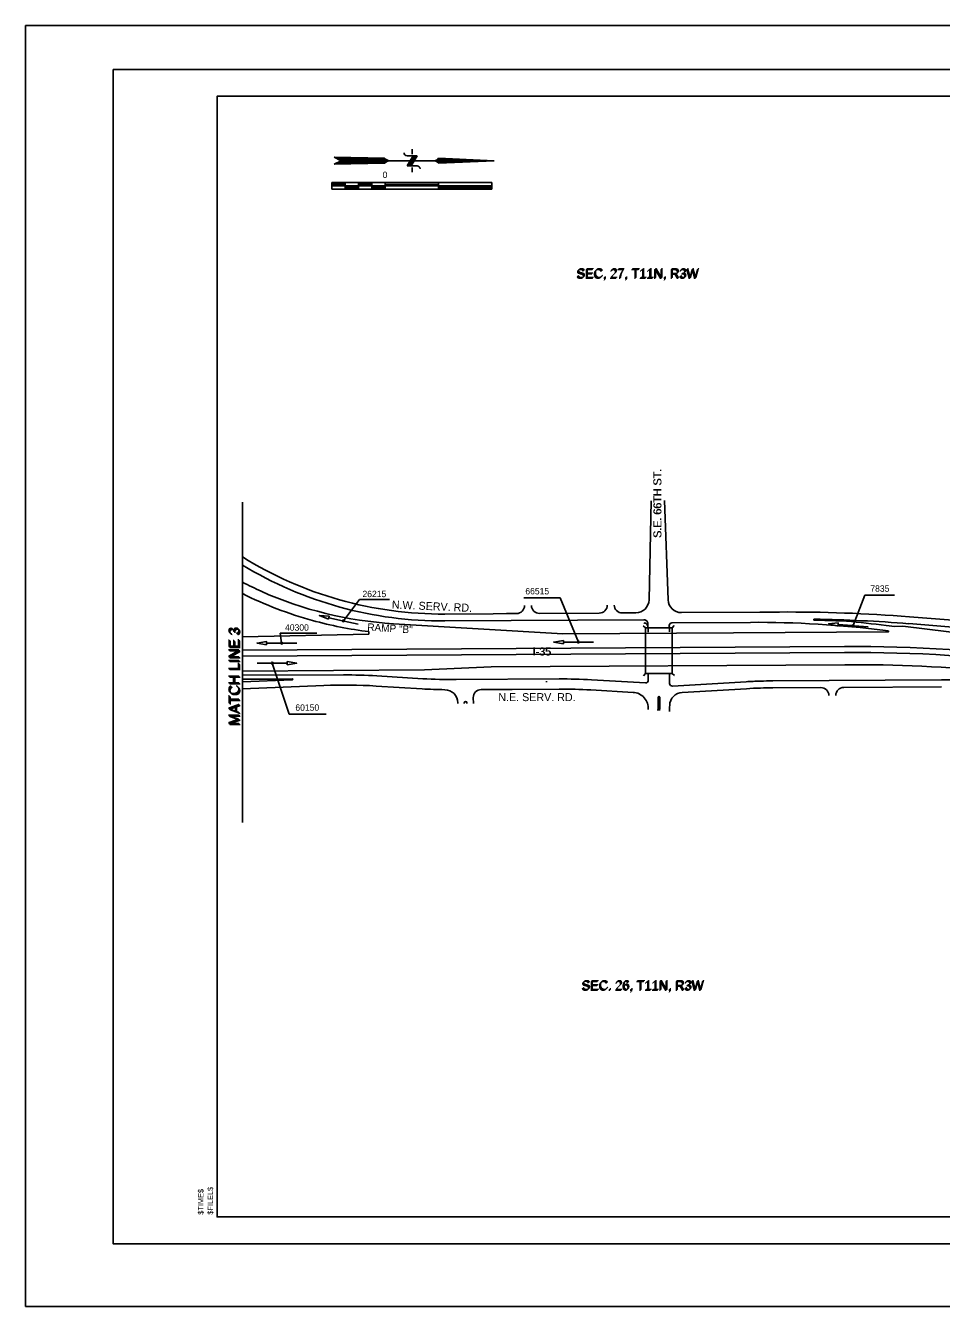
# Model space of a CAD drawing. Extents: x 143344 to 150544, y -2153266 to -2148466.
# Drawn here: x 143344 to 146776, y -2153266 to -2148466 of the extents above; entities that cross this region are included whole.
import ezdxf

# ---------------------------------------------------------------- set-up
doc = ezdxf.new("R2010")
doc.units = 0
for name, color, linetype in [('4', 7, 'Continuous'), ('5', 7, 'Continuous'), ('6', 7, 'Continuous'), ('7', 7, 'Continuous'), ('BASELINE', 7, 'Continuous'), ('Default', 7, 'Continuous'), ('EXIST', 7, 'Continuous'), ('EXPAV', 7, 'Continuous'), ('PROP', 7, 'Continuous'), ('SHT_Plot_Shape_Full', 7, 'Continuous'), ('SHT_Plot_Shape_Half', 7, 'Continuous'), ('SHT_Plot_Stamp', 7, 'Continuous'), ('SHT_Sheet_Border', 7, 'Continuous'), ('T', 7, 'Continuous')]:
    doc.layers.add(name, color=color, linetype=linetype)

# ---------------------------------------------------------------- blocks, each defined once
blk = doc.blocks.new('ARR')
at = {"layer": '6'}
for p, q in [((134, 0), (0, 0)), ((286, 0), (151, 0))]:
    blk.add_line(p, q, dxfattribs=at)
blk.add_lwpolyline([(286, 15), (286, -15), (377, 0)], close=True, dxfattribs=at)
blk.add_circle((143, 0), 8.42, dxfattribs=at)
blk = doc.blocks.new('A')
at = {"layer": 'Default'}
for p, q in [((39, 1057), (65, 1617)), ((65, 1617), (90, 1057)), ((44, 1055), (65, 1490)), ((65, 1007), (65, 1541)), ((85, 1058), (65, 1490)), ((49, 1050), (65, 1378)), ((80, 1050), (65, 1378)), ((55, 1043), (65, 1165)), ((59, 1034), (59, 1271)), ((74, 1043), (65, 1165)), ((70, 1034), (70, 1271)), ((69, 1033), (65, 1093)), ((65, 809), (65, 1007)), ((-2, 789), (-52, 789)), ((14, 839), (14, 738)), ((115, 779), (14, 839)), ((14, 839), (115, 779)), ((14, 834), (115, 773)), ((115, 768), (14, 829)), ((14, 824), (115, 763)), ((115, 758), (14, 819)), ((14, 814), (115, 753)), ((115, 748), (14, 809)), ((14, 804), (115, 743)), ((115, 738), (14, 799)), ((115, 839), (115, 738)), ((181, 789), (131, 789)), ((65, 560), (65, 768)), ((39, 29), (49, 518)), ((44, 39), (54, 527)), ((49, 50), (57, 531)), ((54, 60), (65, 542)), ((59, 70), (59, 536)), ((65, 72), (65, 631)), ((75, 60), (65, 542)), ((80, 50), (70, 537)), ((70, 70), (70, 536)), ((85, 39), (75, 525)), ((90, 29), (80, 519)), ((29, 1), (39, 509)), ((34, 19), (44, 512)), ((95, 19), (85, 512)), ((100, 1), (90, 509)), ((29, 1), (65, 72)), ((65, 72), (100, 1))]:
    blk.add_line(p, q, dxfattribs=at)
for centre, radius, start, end in [((4, 1007), 61, 0, 54.3802), ((125, 1007), 61, 125.6198, 180), ((146, 839), 30.5, 90, 180), ((-17, 738), 30.5, 270, 0), ((-24, 572), 89.2, 314.9567, 352.4189), ((153, 572), 89.2, 187.5811, 225.0433)]:
    blk.add_arc(centre, radius, start, end, dxfattribs=at)
blk = doc.blocks.new('VARROW')
at = {"layer": 'Default', "xscale": 0.00471098, "yscale": 0.00471098}
blk.add_blockref('A', (-0.304, 0.007), dxfattribs=at)
blk = doc.blocks.new('scale')
at = {"layer": 'Default'}
for p, q in [((-3.81, 0.318), (-3.81, 0)), ((-3.81, 0.318), (3.81, 0.318)), ((-3.81, 0.159), (3.81, 0.159)), ((-3.81, 0), (3.81, 0)), ((-3.175, 0.318), (-3.175, 0)), ((-2.54, 0.318), (-2.54, 0)), ((-2.54, 0.318), (-2.54, 0)), ((-1.905, 0.318), (-1.905, 0)), ((-1.27, 0), (-1.27, 0.318)), ((1.27, 0.318), (1.27, 0)), ((1.27, 0), (1.27, 0.318)), ((3.81, 0.318), (3.81, 0))]:
    blk.add_line(p, q, dxfattribs=at)
for points in [[(-3.81, 0.239), (-3.175, 0.239)], [(-3.175, 0.08), (-2.54, 0.08)], [(-2.542, 0.239), (-1.907, 0.239)], [(-1.905, 0.08), (-1.27, 0.08)], [(-1.259, 0.232), (1.276, 0.232)], [(1.27, 0.077), (3.806, 0.077)]]:
    blk.add_lwpolyline(points, dxfattribs=at)
blk.add_text('0', height=0.305, dxfattribs=at).set_placement((-1.398, 0.534))

msp = doc.modelspace()

# ---------------------------------------------------------------- linework, layer by layer
at = {"layer": '6'}
for p, q in [((144535.1, -2150696.7), (144595.3, -2150615.8)), ((144590.8, -2150628.1), (144590.8, -2150628.1)), ((144595.3, -2150615.8), (144707.4, -2150615.8)), ((145347.9, -2150610.4), (145211.7, -2150610.4)), ((145415.9, -2150776), (145347.9, -2150610.4)), ((145347.9, -2150610.4), (145347.9, -2150610.4)), ((146445.3, -2150714.4), (146489.6, -2150600.5)), ((146489.6, -2150600.5), (146489.6, -2150600.5)), ((146489.6, -2150600.5), (146599.9, -2150600.5)), ((144303.8, -2150780), (144297.9, -2150742.4)), ((144297.9, -2150742.4), (144297.9, -2150742.4)), ((144297.9, -2150742.4), (144435.7, -2150742.4)), ((144268.5, -2150855), (144332.3, -2151046.2)), ((144332.3, -2151046.2), (144332.3, -2151046.2)), ((144332.3, -2151046.2), (144470.1, -2151046.2))]:
    msp.add_line(p, q, dxfattribs=at)
at = {"layer": 'BASELINE'}
msp.add_line((144157.2, -2151451.5), (144157.2, -2150251.5), dxfattribs=at)
at = {"layer": 'EXIST'}
for p, q in [((145689, -2150246.1), (145680.4, -2150617.7)), ((145689, -2150246.2), (145680.4, -2150617.7)), ((145739, -2150245.9), (145751.6, -2150617.2)), ((145739, -2150245.9), (145751.6, -2150617.2)), ((145096.1, -2150670.1), (145146.1, -2150669.4)), ((145146.1, -2150669.4), (145184, -2150669.2)), ((145270, -2150668.7), (145494, -2150667.3)), ((145580, -2150666.8), (145630.7, -2150666.5)), ((145801.9, -2150665.5), (146096.1, -2150663.7)), ((146096.1, -2150663.7), (146169.4, -2150663.3)), ((146656.1, -2150681), (146851.2, -2150696.3)), ((145666.6, -2150722.6), (145658.7, -2150714.9)), ((145666.6, -2150722.6), (145716.6, -2150722.3)), ((145667.5, -2150894.2), (145666.6, -2150722.6)), ((145676.5, -2150707.3), (145676.6, -2150738.3)), ((145676.5, -2150719.3), (145676.6, -2150722.5)), ((145716.6, -2150722.3), (145766.6, -2150722.1)), ((145756.5, -2150713.8), (145756.6, -2150737.7)), ((145756.5, -2150713.8), (145756.6, -2150722.1)), ((145766.5, -2150703.7), (146060.4, -2150702)), ((145766.6, -2150722.1), (145774.3, -2150714.2)), ((145766.6, -2150722.1), (145767.5, -2150893.6)), ((146299.8, -2150694), (146419.9, -2150697.7)), ((146566.3, -2150732.5), (146576.7, -2150733.9)), ((146568.7, -2150713.7), (146601.1, -2150717.8)), ((146601.1, -2150717.8), (146631.6, -2150715.7)), ((146631.6, -2150715.7), (147102.9, -2150775.7)), ((146653.9, -2150706.9), (146849.2, -2150722.2)), ((145296.8, -2150922.5), (145296.7, -2150926.5)), ((145464.7, -2150917.3), (145667.1, -2150928.8)), ((145667.5, -2150894.2), (145659.8, -2150902)), ((145717.5, -2150893.9), (145667.5, -2150894.2)), ((145677.5, -2150893.5), (145677.6, -2150918.8)), ((145677.5, -2150894.1), (145677.6, -2150918.8)), ((145767.5, -2150893.6), (145717.5, -2150893.9)), ((145757.5, -2150893.2), (145757.7, -2150930.9)), ((145757.5, -2150893.7), (145757.7, -2150930.9)), ((145767.5, -2150893.6), (145775.3, -2150901.4)), ((145768.3, -2150940.8), (146043.9, -2150924.7)), ((146144.5, -2150921.4), (146775.8, -2150917.6)), ((145051.9, -2150954), (145167.4, -2150953.3)), ((145167.4, -2150953.3), (145343.6, -2150952.3)), ((145462.5, -2150955.3), (145620.6, -2150964.3)), ((145462.5, -2150955.3), (145620.6, -2150964.3)), ((145804.9, -2150964.7), (146045.4, -2150950.6)), ((146144.6, -2150947.4), (146324.2, -2150946.4)), ((146410.2, -2150945.8), (146776, -2150943.6)), ((144964.2, -2151006.2), (144964.2, -2151004.1)), ((144988.2, -2151006), (144988.2, -2151003.9)), ((144998.2, -2151006), (144998.2, -2151003.8)), ((145022.2, -2151005.8), (145022, -2150984.2)), ((145715, -2150982.7), (145715.1, -2150998)), ((145715.9, -2150982.7), (145716, -2150998)), ((145720.2, -2150998), (145720.1, -2150982.7)), ((145721.1, -2150998), (145721, -2150982.7))]:
    msp.add_line(p, q, dxfattribs=at)
for centre, radius, start, end in [((145183.9, -2150639.2), 30, 270.3449, 0.5323), ((145269.9, -2150638.7), 30, 180.5323, 270.3449), ((145493.9, -2150637.3), 30, 270.3449, 0.5324), ((145579.8, -2150636.8), 30, 180.5324, 270.3449), ((145630.4, -2150616.5), 50, 270.3449, 358.6743), ((145630.4, -2150616.5), 50, 270.3449, 358.6743), ((145801.6, -2150615.5), 50, 181.9475, 270.3434), ((145801.6, -2150615.5), 50, 181.9475, 270.3434), ((146203.9, -2156405.8), 5742.6, 85.48343, 90.34434), ((145661.5, -2150719.3), 15, 0.3109, 90.3443), ((145766.5, -2150713.7), 10, 90.3443, 180.3109), ((145766.5, -2150713.7), 10, 90.3442, 180.3109), ((146083.4, -2154521.6), 3819.7, 82.7361, 90.3443), ((146299.9, -2150692), 2, 89.0371, 266.7638), ((146203.9, -2156405.8), 5716.6, 85.4846, 89.0371), ((146083.4, -2154521.6), 3838.7, 82.7361, 84.9703), ((146449, -2156533.3), 5740.6, 82.52117, 90.35541), ((146449, -2156533.3), 5718.6, 82.5212, 90.3554), ((146449, -2156533.3), 5672.6, 84.5212, 90.3555), ((145667.6, -2150918.8), 10, 266.749, 0.3109), ((145667.6, -2150918.8), 10, 266.749, 0.3109), ((146156, -2152844.3), 1922.9, 91.7412, 93.344), ((146156, -2152844.3), 1922.9, 90.3443, 91.7413), ((144945.9, -2149044.8), 1909.9, 266.5225, 269.0712), ((144914.2, -2151004.4), 50, 0.3442, 89.0712), ((145052, -2150984), 30, 90.3442, 180.3442), ((145355, -2152849.1), 1896.9, 86.749, 90.3443), ((145355, -2152849.1), 1896.9, 86.749, 90.3442), ((145617.2, -2151024.2), 60, 355.7085, 86.749), ((145617.2, -2151024.2), 60, 355.7085, 86.749), ((145767.7, -2150930.8), 10, 180.3109, 273.344), ((145767.7, -2150930.8), 10, 180.3109, 273.344), ((145807.8, -2151014.6), 50, 93.344, 178.17), ((145807.8, -2151014.6), 50, 93.344, 178.17), ((146156, -2152844.3), 1896.9, 91.7604, 93.344), ((146156, -2152844.3), 1896.9, 90.3443, 91.7605), ((146324.4, -2150976.4), 30, 0.3443, 90.3443), ((146410.4, -2150975.8), 30, 90.3443, 180.3443), ((144993.2, -2151003.9), 5, 0.3442, 180.3442), ((145299.2, -2151000.5), 415.9, 355.6767, 0.3443), ((145299.2, -2151000.5), 416.8, 355.6767, 0.3443), ((145718, -2150982.7), 3, 0.3443, 180.3443), ((145718, -2150982.7), 2.1, 0.3443, 180.3443), ((145299.2, -2151000.5), 421, 355.6668, 0.3443), ((145299.2, -2151000.5), 421.9, 355.6668, 0.3443), ((145350.5, -2151000), 407.6, 354.9844, 358.17), ((145350.5, -2151000), 407.6, 354.9844, 358.17)]:
    msp.add_arc(centre, radius, start, end, dxfattribs=at)
at = {"layer": 'EXPAV'}
msp.add_arc((146793.1, -2153795.4), 2877.8, 76.627, 90.3443, dxfattribs=at)
at = {"layer": 'PROP'}
for p, q in [((144915.2, -2150670.8), (145096.1, -2150669.7)), ((145357.4, -2150745.2), (144722.6, -2150707.1)), ((144915.3, -2150696.8), (145661.4, -2150692.4)), ((144156.9, -2150756.4), (144630.6, -2150746.8)), ((144630.6, -2150746.8), (144630.6, -2150736.8)), ((145357.4, -2150745.2), (145996.7, -2150741.3)), ((145996.7, -2150741.3), (146576.5, -2150737.8)), ((144156.9, -2150806.4), (146413.4, -2150792.8)), ((144156.9, -2150828.4), (146413.5, -2150814.8)), ((144838.8, -2150880.3), (145088.7, -2150868.8)), ((145088.7, -2150868.8), (146413.8, -2150860.8)), ((144156.9, -2150884.4), (144838.8, -2150880.3)), ((144156.9, -2150900.3), (144535.8, -2150899.1)), ((144156.9, -2150915.3), (144293.1, -2150914.9)), ((144156.9, -2150925.5), (144343.2, -2150917.7)), ((144293.1, -2150914.9), (144343.1, -2150913.7)), ((144660.1, -2150902.7), (144832.4, -2150913.2)), ((144957.2, -2150916.6), (145343.3, -2150914.3)), ((144156.9, -2150951.5), (144462.1, -2150938.8)), ((144657.8, -2150940.6), (144830.1, -2150951.1))]:
    msp.add_line(p, q, dxfattribs=at)
for centre, radius, start, end in [((144906.6, -2149251.5), 1419.4, 238.1139, 270.3443), ((144906.6, -2149251.5), 1445.4, 238.7529, 270.3443), ((144690.8, -2149548.7), 1135.9, 241.9614, 245.8859), ((144807.9, -2149287.2), 1422.4, 245.8859, 266.5648), ((144807.9, -2149287.2), 1460.4, 243.5274, 254.5648), ((144807.9, -2149287.2), 1460.4, 254.5648, 263.0262), ((145661.5, -2150707.4), 15, 0.3111, 90.3429), ((146576.5, -2150735.8), 2, 270.3443, 82.7363), ((144343.1, -2150915.7), 2, 272.394, 91.3276), ((144343.1, -2150915.7), 2, 272.394, 91.3276), ((144541.9, -2152847), 1947.9, 86.5225, 90.1813), ((144945.9, -2149044.8), 1871.9, 266.5225, 270.3443), ((145355, -2152849.1), 1934.9, 86.749, 90.3443), ((144541.9, -2152847), 1909.9, 86.5225, 92.394)]:
    msp.add_arc(centre, radius, start, end, dxfattribs=at)
at = {"layer": 'SHT_Plot_Shape_Full'}
msp.add_lwpolyline([(143344.4, -2148465.6), (150544.4, -2148465.6), (150544.4, -2153265.6), (143344.4, -2153265.6)], close=True, dxfattribs=at)
at = {"layer": 'SHT_Plot_Shape_Half'}
msp.add_lwpolyline([(143671.9, -2148630.6), (150471.9, -2148630.6), (150471.9, -2153030.6), (143671.9, -2153030.6)], close=True, dxfattribs=at)
at = {"layer": 'SHT_Sheet_Border'}
msp.add_lwpolyline([(150361.9, -2152930.6), (144061.9, -2152930.6), (144061.9, -2148730.6), (150361.9, -2148730.6)], close=True, dxfattribs=at)

# ---------------------------------------------------------------- block references
at = {"layer": '6'}
for p, xscale, yscale, rotation in [((144590, -2150708.9), 0.39370000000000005, 0.39369999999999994, 167.46022459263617), ((146501.4, -2150718.8), 0.3937000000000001, 0.39370000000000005, 175.49002624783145), ((144360.1, -2150780), 0.39370000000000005, 0.3937000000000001, 180), ((145472.1, -2150776), 0.39370000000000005, 0.3937000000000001, 180)]:
    msp.add_blockref('ARR', p, dxfattribs=dict(at, xscale=xscale, yscale=yscale, rotation=rotation))
at = {"layer": '6', "xscale": 0.39370000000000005, "yscale": 0.3937000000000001}
msp.add_blockref('ARR', (144212.2, -2150855), dxfattribs=at)
at = {"layer": '7', "xscale": 78.74000000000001, "yscale": 78.74000000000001, "rotation": -90.00000000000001}
msp.add_blockref('VARROW', (144499.3, -2148972.1), dxfattribs=at)
at = {"layer": '7', "xscale": 78.74000000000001, "yscale": 78.74000000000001}
msp.add_blockref('scale', (144792, -2149078.9), dxfattribs=at)

# ---------------------------------------------------------------- texts
at = {"layer": '4'}
msp.add_text('RAMP "B"', height=28, rotation=356.5106, dxfattribs=at).set_placement((144624.1, -2150733.2))
at = {"layer": '5'}
for s, height, p in [('SEC, 27, T11N, R3W', 36, (145406.5, -2149415)), ('SEC, 27, T11N, R3W', 36, (145408, -2149413.4)), ('SEC, 27, T11N, R3W', 36, (145409.6, -2149411.9)), ('SEC, 27, T11N, R3W', 36, (145411.2, -2149410.3)), ('I-35', 30, (145243.7, -2150826.2)), ('I-35', 30, (145245.7, -2150826.2)), ('N.E. SERV. RD.', 30, (145115.7, -2150997.3)), ('SEC. 26, T11N, R3W', 36, (145425.7, -2152083)), ('SEC. 26, T11N, R3W', 36, (145427.2, -2152081.4)), ('SEC. 26, T11N, R3W', 36, (145428.8, -2152079.9)), ('SEC. 26, T11N, R3W', 36, (145430.4, -2152078.3))]:
    msp.add_text(s, height=height, dxfattribs=at).set_placement(p)
for s, rotation, p in [('S.E. 66TH ST.', 90, (145726.8, -2150384.2)), ('S.E. 66TH ST.', 90, (145726.8, -2150386.2)), ('N.W. SERV. RD.', 357.5577, (144716.1, -2150650.1))]:
    msp.add_text(s, height=30, rotation=rotation, dxfattribs=at).set_placement(p)
at = {"layer": 'SHT_Plot_Stamp'}
for s, p in [('$TIME$', (144010.9, -2152922.1)), ('$FILEL$', (144046.4, -2152922.1))]:
    msp.add_text(s, height=20, rotation=90, dxfattribs=at).set_placement(p)
at = {"layer": 'T'}
for s, p in [('26215', (144606.6, -2150607.6)), ('66515', (145216.9, -2150597.3)), ('7835', (146509.7, -2150587.4)), ('40300', (144316.5, -2150733.3)), ('60150', (144355.2, -2151033.3))]:
    msp.add_text(s, height=24, dxfattribs=at).set_placement(p)
for p in [(144143.9, -2151086.3), (144145.7, -2151088.2), (144147.6, -2151090), (144149.4, -2151091.8)]:
    msp.add_text('MATCH LINE 3', height=40, rotation=90, dxfattribs=at).set_placement(p)

doc.saveas('drawing.dxf')
